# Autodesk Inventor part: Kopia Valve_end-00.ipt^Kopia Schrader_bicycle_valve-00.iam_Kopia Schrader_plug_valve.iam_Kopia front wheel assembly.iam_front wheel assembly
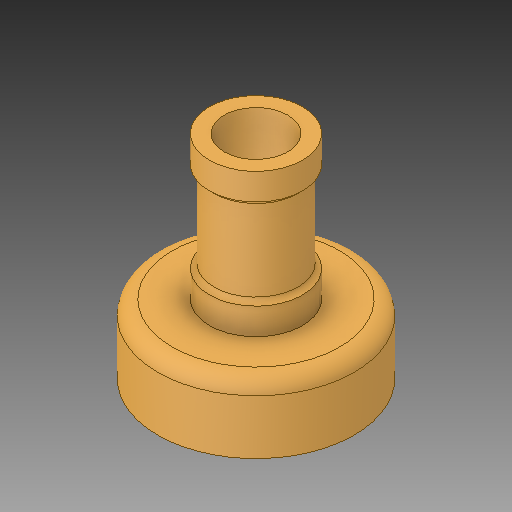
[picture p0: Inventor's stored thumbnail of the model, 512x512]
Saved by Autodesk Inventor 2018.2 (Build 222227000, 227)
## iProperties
Created: 2017-09
Part Number: Kopia Valve_end-00.ipt^Kopia Schrader_bicycle_valve-00.iam_Kopia Schrader_plug_valve.iam_Kopia front wheel assembly.iam_front wheel assembly
Material: Ogólny
Document SubType Name: Modeling
Designer: Tomasz
Density: 1 g/cm^3
Appearance: Domyślna
Author: Tomasz
Sending System: SolidWorks 2017
Last Author: Tomasz
Last Saved: 2017-09-11
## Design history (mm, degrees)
feature "Valve_end-00.ipt"
node "Bryła1"
